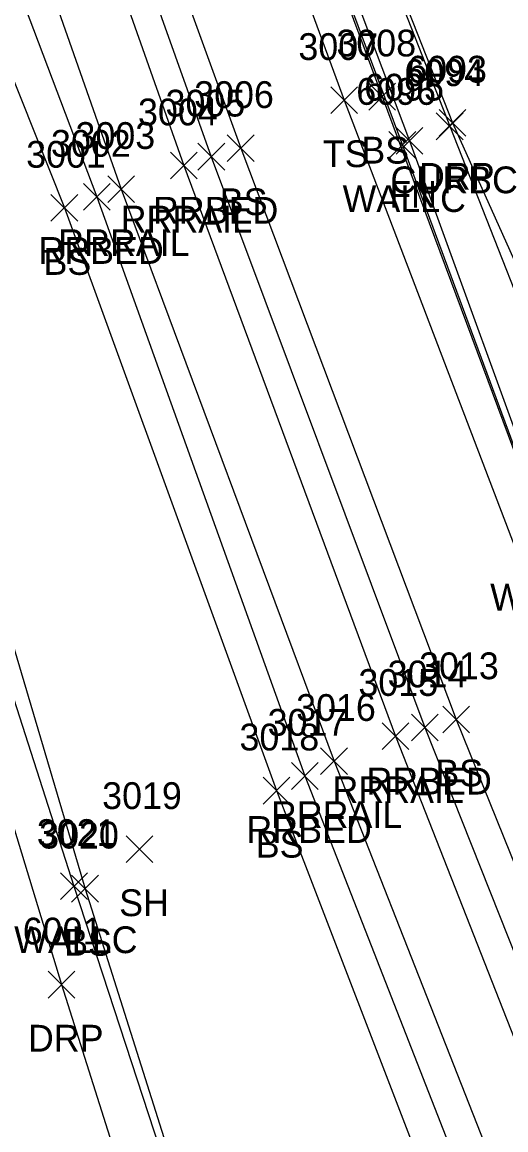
# Model space of a CAD drawing. Extents: x 1462668 to 1465147, y 550359 to 557351.
# Drawn here: x 1464443.6 to 1464479.7, y 553095.9 to 553178.6 of the extents above; entities that cross this region are included whole.
import ezdxf

# ---------------------------------------------------------------- set-up
doc = ezdxf.new("R2010")
doc.units = 0
for name, color, linetype in [('L_A', 7, 'Continuous'), ('L_I', 7, 'Continuous'), ('L_TIC', 7, 'Continuous'), ('LELB', 7, 'Continuous'), ('LFNC', 7, 'Continuous'), ('LW', 7, 'Continuous'), ('R_A', 7, 'Continuous'), ('R_I', 7, 'Continuous'), ('R_TIC', 7, 'Continuous'), ('RC', 7, 'Continuous'), ('RDP', 7, 'Continuous'), ('RR', 7, 'Continuous'), ('RRB', 7, 'Continuous')]:
    doc.layers.add(name, color=color, linetype=linetype)

msp = doc.modelspace()

# ---------------------------------------------------------------- linework, layer by layer
at = {"layer": 'L_TIC'}
for points in [[(1464466.607, 553171.811), (1464468.607, 553173.811)], [(1464468.607, 553171.811), (1464466.607, 553173.811)], [(1464469.447, 553172.076), (1464471.447, 553174.076)], [(1464471.447, 553172.076), (1464469.447, 553174.076)], [(1464458.878, 553168.226), (1464460.878, 553170.226)], [(1464460.878, 553168.226), (1464458.878, 553170.226)], [(1464470.952, 553168.463), (1464472.952, 553170.463)], [(1464472.952, 553168.463), (1464470.952, 553170.463)], [(1464471.493, 553168.782), (1464473.493, 553170.782)], [(1464473.493, 553168.782), (1464471.493, 553170.782)], [(1464445.714, 553163.768), (1464447.714, 553165.768)], [(1464447.714, 553163.768), (1464445.714, 553165.768)], [(1464474.977, 553125.575), (1464476.977, 553127.575)], [(1464476.977, 553125.575), (1464474.977, 553127.575)], [(1464461.562, 553120.255), (1464463.562, 553122.255)], [(1464463.562, 553120.255), (1464461.562, 553122.255)], [(1464451.315, 553115.884), (1464453.315, 553117.884)], [(1464453.315, 553115.884), (1464451.315, 553117.884)], [(1464446.428, 553113.122), (1464448.428, 553115.122)], [(1464448.428, 553113.122), (1464446.428, 553115.122)], [(1464447.257, 553112.934), (1464449.257, 553114.934)], [(1464449.257, 553112.934), (1464447.257, 553114.934)]]:
    msp.add_lwpolyline(points, dxfattribs=at)
at = {"layer": 'LELB'}
for points in [[(1464320.567, 553552.858), (1464335.76, 553496.578), (1464351.011, 553439.579), (1464352.003, 553433.56), (1464356.912, 553435.892), (1464366.085, 553404.903), (1464375.786, 553365.63), (1464378.907, 553354.302), (1464392.497, 553314.304), (1464410.738, 553264.077), (1464424.646, 553220.178), (1464446.714, 553164.768), (1464462.562, 553121.255), (1464478.696, 553079.343), (1464487.037, 553051.034), (1464509.441, 553004.952), (1464519.166, 552979.765), (1464533.373, 552948.388), (1464548.853, 552915.726), (1464568.294, 552875.055), (1464587.074, 552834.384)], [(1464399.719, 553434.969), (1464409.446, 553421.214), (1464402.249, 553418.234), (1464397.039, 553410.685), (1464397.409, 553402.739), (1464404.988, 553402.374), (1464405.18, 553391.163), (1464405.505, 553357.551), (1464416.93, 553321.523), (1464428.808, 553284.849), (1464433.809, 553271.259), (1464449.256, 553230.015), (1464470.447, 553173.076), (1464486.562, 553129.804), (1464498.303, 553097.82), (1464507.971, 553103.591)], [(1464352.266, 553411.5), (1464356.501, 553400.304), (1464368.337, 553363.69), (1464370.812, 553354.985), (1464381.038, 553323.469), (1464386.209, 553306.701), (1464401.249, 553260.464), (1464415.251, 553216.979), (1464434.488, 553160.379), (1464448.257, 553113.934), (1464461.865, 553070.969), (1464468.271, 553054.084), (1464475.246, 553046.499), (1464486.324, 553025.812), (1464494.289, 553015.43), (1464501.885, 553003.229), (1464511.534, 552976.03), (1464526.794, 552944.898), (1464544.104, 552913.881)], [(1464428.808, 553284.849), (1464422.115, 553282.842), (1464423.965, 553275.296), (1464439.307, 553225.795), (1464459.878, 553169.226), (1464475.977, 553126.575), (1464492.566, 553085.469), (1464504.194, 553058.693), (1464521.817, 553014.257)], [(1464433.809, 553271.259), (1464446.9, 553229.17), (1464467.607, 553172.811), (1464484.275, 553129.168), (1464495.72, 553097.092), (1464504.824, 553079.502), (1464512.152, 553060.642), (1464527.258, 553022.24), (1464542.187, 552990.027), (1464554.676, 552968.433)]]:
    msp.add_lwpolyline(points, dxfattribs=at)
at = {"layer": 'LFNC'}
msp.add_lwpolyline([(1464405.682, 553401.697), (1464406.125, 553357.815), (1464412.915, 553336.379), (1464424.414, 553300.548), (1464435.201, 553269.165), (1464460.504, 553201.526), (1464472.493, 553169.782), (1464483.318, 553139.998), (1464499.045, 553098.909), (1464526.004, 553115.935), (1464547.488, 553129.548)], dxfattribs=at)
at = {"layer": 'LW'}
for points in [[(1464405.978, 553402.257), (1464405.239, 553402.286), (1464405.602, 553357.557), (1464412.384, 553336.293), (1464423.999, 553300.426), (1464435.008, 553269.098), (1464460.101, 553201.294), (1464471.952, 553169.463), (1464482.975, 553139.703), (1464498.654, 553098.241), (1464526.685, 553115.597)], [(1464414.868, 553216.81), (1464432.856, 553159.415), (1464447.428, 553114.122), (1464461.56, 553070.894), (1464467.281, 553053.839), (1464469.978, 553045.082), (1464479.637, 553018.49)]]:
    msp.add_lwpolyline(points, dxfattribs=at)
at = {"layer": 'R_TIC'}
for points in [[(1464474.487, 553169.86), (1464476.487, 553171.86)], [(1464476.487, 553169.86), (1464474.487, 553171.86)], [(1464474.704, 553170.123), (1464476.704, 553172.123)], [(1464476.704, 553170.123), (1464474.704, 553172.123)], [(1464456.686, 553167.589), (1464458.686, 553169.589)], [(1464458.686, 553167.589), (1464456.686, 553169.589)], [(1464454.628, 553166.93), (1464456.628, 553168.93)], [(1464456.628, 553166.93), (1464454.628, 553168.93)], [(1464449.962, 553165.17), (1464451.962, 553167.17)], [(1464451.962, 553165.17), (1464449.962, 553167.17)], [(1464448.131, 553164.586), (1464450.131, 553166.586)], [(1464450.131, 553164.586), (1464448.131, 553166.586)], [(1464470.443, 553124.328), (1464472.443, 553126.328)], [(1464472.443, 553124.328), (1464470.443, 553126.328)], [(1464472.625, 553124.967), (1464474.625, 553126.967)], [(1464474.625, 553124.967), (1464472.625, 553126.967)], [(1464465.848, 553122.461), (1464467.848, 553124.461)], [(1464467.848, 553122.461), (1464465.848, 553124.461)], [(1464463.664, 553121.352), (1464465.664, 553123.352)], [(1464465.664, 553121.352), (1464463.664, 553123.352)], [(1464445.501, 553105.77), (1464447.501, 553107.77)], [(1464447.501, 553105.77), (1464445.501, 553107.77)]]:
    msp.add_lwpolyline(points, dxfattribs=at)
at = {"layer": 'RC'}
msp.add_lwpolyline([(1464468.543, 553237.575), (1464466.946, 553228.645), (1464465.47, 553220.99), (1464463.446, 553209.787), (1464463.998, 553203.305), (1464467.134, 553192.194), (1464475.487, 553170.86), (1464484.246, 553148.657), (1464487.641, 553142.28), (1464490.994, 553136.627), (1464495.503, 553130.929), (1464500.963, 553127.103), (1464507.415, 553124.697), (1464516.221, 553124.149), (1464522.071, 553124.782), (1464532.396, 553129.483), (1464542.271, 553135.894)], dxfattribs=at)
at = {"layer": 'RDP'}
for points in [[(1464415.79, 553337.749), (1464428.461, 553302.553), (1464440.386, 553270.852), (1464449.423, 553250.026), (1464452.476, 553249.02), (1464464.043, 553246.033), (1464467.802, 553242.215), (1464468.817, 553237.697), (1464467.194, 553228.459), (1464465.771, 553220.817), (1464463.821, 553209.815), (1464464.173, 553203.329), (1464467.407, 553192.18), (1464475.704, 553171.123), (1464491.179, 553136.657), (1464495.726, 553131.043), (1464500.877, 553127.317), (1464507.408, 553124.811), (1464516.194, 553124.19), (1464522.185, 553124.998), (1464532.312, 553129.713), (1464542.149, 553136.009)], [(1464420.974, 553189.368), (1464433.488, 553149.529), (1464446.501, 553106.77), (1464473.633, 553021.093), (1464478.486, 553000.048)]]:
    msp.add_lwpolyline(points, dxfattribs=at)
at = {"layer": 'RR'}
for points in [[(1464329.227, 553555.383), (1464346.959, 553499.526), (1464365.931, 553439.424), (1464375.443, 553408.882), (1464392.353, 553356.138), (1464404.616, 553317.704), (1464421.027, 553267.802), (1464435.667, 553224.383), (1464455.628, 553167.93), (1464471.443, 553125.328), (1464488.07, 553083.008), (1464498.631, 553056.822), (1464517.453, 553011.952), (1464529.395, 552984.226), (1464543.059, 552953.498), (1464558.282, 552920.118), (1464577.458, 552878.669), (1464596.621, 552838.046)], [(1464324.555, 553553.944), (1464342.167, 553498.072), (1464361.292, 553437.522), (1464370.776, 553407.016), (1464387.3, 553355.343), (1464399.888, 553316.176), (1464416.453, 553266.264), (1464431.113, 553222.566), (1464450.962, 553166.17), (1464466.848, 553123.461), (1464483.538, 553081.048), (1464493.972, 553055.168), (1464513.542, 553008.432), (1464524.983, 552981.815), (1464538.762, 552951.059), (1464553.982, 552917.82), (1464573.128, 552876.248), (1464592.225, 552835.923)]]:
    msp.add_lwpolyline(points, dxfattribs=at)
at = {"layer": 'RRB'}
for points in [[(1464320.567, 553552.858), (1464339.05, 553497.299), (1464359.102, 553436.849), (1464368.452, 553406.111), (1464384.327, 553354.986), (1464397.563, 553315.408), (1464413.048, 553265.366), (1464427.983, 553221.445), (1464449.131, 553165.586), (1464464.664, 553122.352), (1464481.224, 553080.022), (1464490.894, 553052.761), (1464510.863, 553007.552), (1464522.316, 552980.594), (1464536.188, 552949.724), (1464551.426, 552916.631), (1464570.989, 552875.749), (1464590.293, 552834.942)], [(1464345.31, 553519.908), (1464352.279, 553501.122), (1464369.887, 553440.754), (1464378.638, 553409.812), (1464396.8, 553355.407), (1464407.98, 553318.651), (1464422.767, 553268.535), (1464437.567, 553224.949), (1464457.686, 553168.589), (1464473.625, 553125.967), (1464490.255, 553084.118), (1464501.176, 553057.708), (1464519.383, 553013.043), (1464531.698, 552984.969), (1464545.352, 552954.916), (1464560.689, 552920.935), (1464579.899, 552880.239), (1464598.79, 552838.414)]]:
    msp.add_lwpolyline(points, dxfattribs=at)

# ---------------------------------------------------------------- texts
at = {"layer": 'L_A'}
for s, p in [('BS', (1464468.888, 553168.076)), ('TS', (1464466.017, 553167.811)), ('FN', (1464470.974, 553164.782)), ('BS', (1464458.319, 553164.226)), ('WALLC', (1464467.488, 553164.463)), ('BS', (1464445.155, 553159.768)), ('WALLC', (1464478.51, 553134.703)), ('BS', (1464474.418, 553121.575)), ('BS', (1464461.003, 553116.255)), ('SH', (1464450.803, 553111.884)), ('WALLC', (1464442.963, 553109.122)), ('BS', (1464446.698, 553108.934))]:
    msp.add_text(s, height=2, dxfattribs=at).set_placement(p)
at = {"layer": 'L_I'}
for s, p in [('3007', (1464464.19, 553175.811)), ('3008', (1464467.03, 553176.076)), ('3006', (1464456.406, 553172.226)), ('6096', (1464468.511, 553172.463)), ('6095', (1464469.108, 553172.782)), ('3001', (1464443.863, 553167.768)), ('3013', (1464473.205, 553129.575)), ('3018', (1464459.791, 553124.255)), ('3019', (1464449.535, 553119.884)), ('3021', (1464444.656, 553117.122)), ('3020', (1464444.832, 553116.934))]:
    msp.add_text(s, height=2, dxfattribs=at).set_placement(p)
at = {"layer": 'R_A'}
for s, p in [('CURBC', (1464471.069, 553165.86)), ('DRP', (1464473.192, 553166.123)), ('RRBED', (1464453.331, 553163.589)), ('RRRAIL', (1464450.919, 553162.93)), ('RRRAIL', (1464446.253, 553161.17)), ('RRBED', (1464444.776, 553160.586)), ('RRBED', (1464469.271, 553120.967)), ('RRRAIL', (1464466.735, 553120.328)), ('RRRAIL', (1464462.139, 553118.461)), ('RRBED', (1464460.309, 553117.352)), ('DRP', (1464443.99, 553101.77))]:
    msp.add_text(s, height=2, dxfattribs=at).set_placement(p)
at = {"layer": 'R_I'}
for s, p in [('6094', (1464472.101, 553173.86)), ('6093', (1464472.318, 553174.123)), ('3005', (1464454.268, 553171.589)), ('3004', (1464452.211, 553170.93)), ('3003', (1464447.544, 553169.17)), ('3002', (1464445.713, 553168.586)), ('3014', (1464470.853, 553128.967)), ('3015', (1464468.672, 553128.328)), ('3016', (1464464.021, 553126.461)), ('3017', (1464461.892, 553125.352)), ('6001', (1464443.604, 553109.77))]:
    msp.add_text(s, height=2, dxfattribs=at).set_placement(p)

doc.saveas('drawing.dxf')
